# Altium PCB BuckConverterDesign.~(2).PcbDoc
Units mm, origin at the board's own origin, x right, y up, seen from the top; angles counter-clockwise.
Board outline 71.7 x 34.6 mm, 4 copper layers (Top Layer, IN-1, IN-2, Bottom Layer), stack 0.603 mm thick; 42 components, 34 nets, 154 pads, 18 vias.
Unrouted connection lines stored in the file: 68.
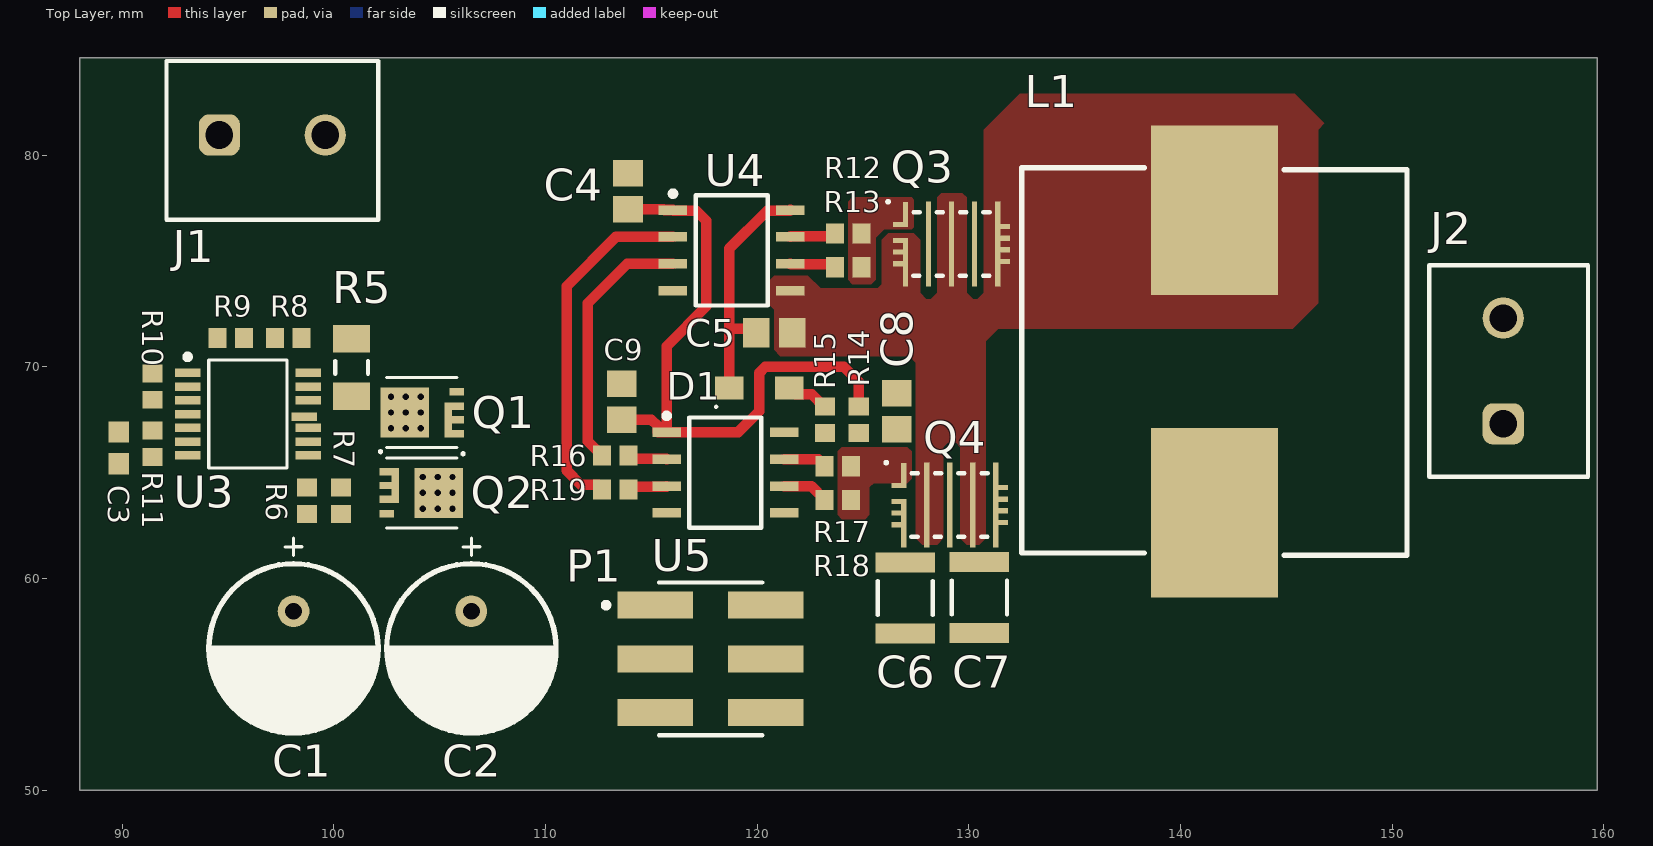
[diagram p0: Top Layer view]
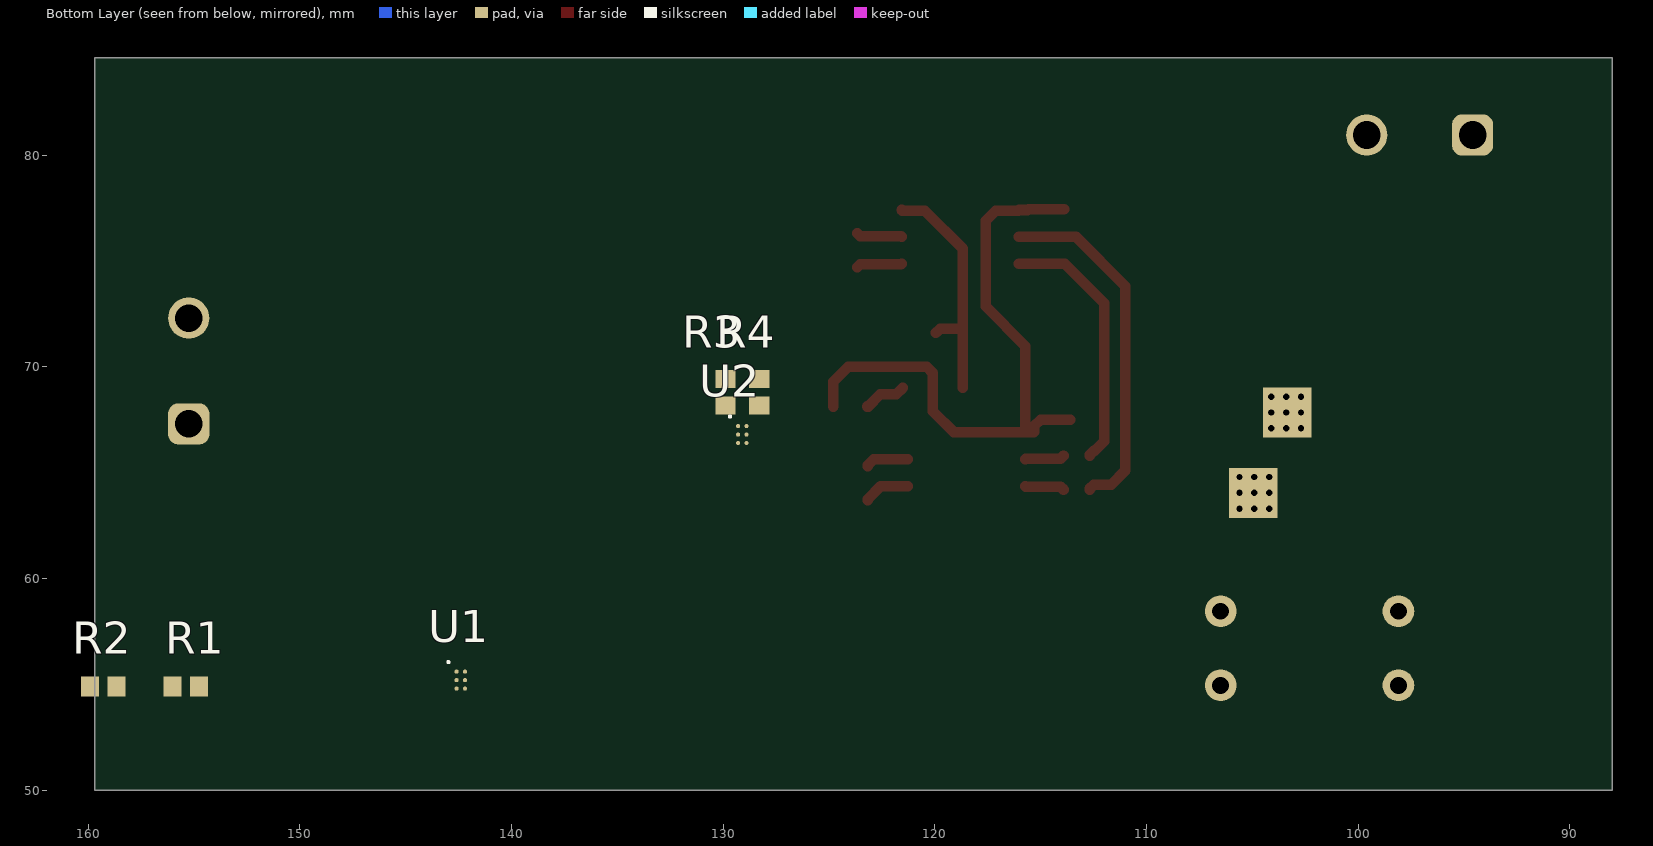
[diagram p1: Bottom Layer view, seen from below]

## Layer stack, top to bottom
Top Solder: solder mask 0.0102, Solder Resist, Dk 3.5
Top Layer: signal copper 0.035
Dielectric 2: prepreg 0.0711, PP-006, Dk 4.1
IN-1: signal copper 0.0356
Dielectric 1: dielectric 0.32, FR-4, Dk 4.8
IN-2: signal copper 0.0356
Dielectric 3: prepreg 0.0711, PP-006, Dk 4.1
Bottom Layer: signal copper 0.035
Bottom Solder: solder mask 0.0102, Solder Resist, Dk 3.5

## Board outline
88,50 159.7,50 159.7,84.6 88,84.6

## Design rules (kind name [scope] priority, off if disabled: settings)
AssemblyTestPointUsage [All] p1: isadvanced=TRUE
AssemblyTestpoint [All] p1: isadvanced=TRUE testpointundercomponent=TRUE minsize=1.016 maxsize=2.54 preferedsize=1.524 minholesize=0 maxholesize=1.016 preferedholesize=0.813 testpointgrid=0.025 usegrid=TRUE gridtolerance=0 allowsidetop=TRUE allowsidebottom=TRUE
Clearance Clearance_1 [All] p1: isadvanced=TRUE gap=0.15 ignorepadtopadclearanceinfootprint=FALSE
Clearance [All] p2: gap=0.254 ignorepadtopadclearanceinfootprint=FALSE ismatrix=TRUE
ComponentClearance [All] p1: isadvanced=TRUE gap=0.254 collisioncheckmode=3 verticalgap=0.254 showdistances=FALSE
FabricationTestPointUsage [All] p1: isadvanced=TRUE valid=0 allowmultiple=FALSE
FabricationTestpoint [All] p1: isadvanced=TRUE side=3 testpointundercomponent=TRUE minsize=1.016 maxsize=2.54 preferedsize=1.524 minholesize=0 maxholesize=1.016 preferedholesize=0.813 testpointgrid=0.025 allowsidetop=TRUE allowsidebottom=TRUE usegrid=TRUE gridtolerance=0
FanoutControl Fanout_BGA [IsBGA] p1: isadvanced=TRUE bgadir=Out bgaviamode=Centered fanoutstyle=Auto fanoutdirection=Alternating viagrid=0.025 // Fanout_BGA (Default Rule)
FanoutControl Fanout_LCC [IsLCC] p2: isadvanced=TRUE bgadir=Out bgaviamode=Centered fanoutstyle=Auto fanoutdirection=Alternating viagrid=0.025 // Fanout_LCC (Default Rule)
FanoutControl Fanout_SOIC [IsSOIC] p3: isadvanced=TRUE bgadir=Out bgaviamode=Centered fanoutstyle=Auto fanoutdirection=Alternating viagrid=0.025 // Fanout_SOIC (Default Rule)
FanoutControl Fanout_Small [(CompPinCount < 5)] p4: isadvanced=TRUE bgadir=Out bgaviamode=Centered fanoutstyle=Auto fanoutdirection=OutThenIn viagrid=0.025 // Fanout_Small (Default Rule)
FanoutControl Fanout_Default [All] p5: isadvanced=TRUE bgadir=Out bgaviamode=Centered fanoutstyle=Auto fanoutdirection=Alternating viagrid=0.025 // Fanout_Default (Default Rule)
Height [All] p1: isadvanced=TRUE minheight=0 maxheight=25.4 prefheight=12.7
HoleSize [All] p1: isadvanced=TRUE absolutevalues=TRUE maxlimit=20 minlimit=0.3 maxpercent=80.000 minpercent=20.000
HoleToHoleClearance [All] p1: isadvanced=TRUE gap=0.3 allowstackedmicrovias=TRUE
LayerPairs [All] p1: isadvanced=TRUE enforce=TRUE
MinimumSolderMaskSliver [All] p1: isadvanced=TRUE minsoldermaskwidth=0.15
NetAntennae [All] p1: isadvanced=TRUE netantennaetolerance=0
PasteMaskExpansion [All] p1: isadvanced=TRUE expansion=0.1 thpadusetoppaste=TRUE thpadusebottompaste=TRUE
PlaneClearance [All] p1: isadvanced=TRUE clearance=0.508
PlaneConnect [All] p1: isadvanced=TRUE planeconnectstyle=Relief reliefexpansion=0.508 reliefentries=4 reliefconductorwidth=0.254 reliefairgap=0.254
RoutingCorners [All] p1: isadvanced=TRUE cornerstyle=45-Degree minsetback=2.54 maxsetback=2.54
RoutingPriority [All] p1: isadvanced=TRUE routingpriority=0
RoutingTopology RoutingTopology_1 [All] p1: isadvanced=TRUE topology=Daisy_Balanced
RoutingVias RoutingViaStyle_1 [All] p1: isadvanced=TRUE holewidth=0.3 width=0.5 viastyle="Through Hole" minholewidth=0.3 minwidth=0.5 maxholewidth=10 maxwidth=20
RoutingVias [All] p2: holewidth=0.711 width=1.27 viastyle="Through Hole" minholewidth=0.711 minwidth=1.27 maxholewidth=0.711 maxwidth=1.27
ShortCircuit [All] p1: isadvanced=TRUE allowed=FALSE
SilkToSilkClearance [All] p1: isadvanced=TRUE silktosilkclearance=0.15
SilkToSolderMaskClearance [IsPad] p1: isadvanced=TRUE minsilkscreentomaskgap=0.15 clearancetoexposedcopper=TRUE
SolderMaskExpansion [All] p1: isadvanced=TRUE expansion=0.102 istentingtop=TRUE
SupplyNets "Schematic Supply Nets_13" [InNet('VOUT')] p1: voltage=0.000
SupplyNets "Schematic Supply Nets_12" [InNet('3V3')] p2: voltage=0.000
SupplyNets "Schematic Supply Nets_11" [InNet('VIN')] p3: voltage=0.000
SupplyNets "Schematic Supply Nets_10" [InNet('OUT')] p4: voltage=0.000
SupplyNets "Schematic Supply Nets_9" [InNet('5V')] p5: voltage=0.000
SupplyNets "Schematic Supply Nets_2" [InNet('GND')] p6: voltage=0.000
SupplyNets "Schematic Supply Nets_1" [InNet('SW Node')] p7: voltage=0.000
UnRoutedNet [All] p1: isadvanced=TRUE
UnpouredPolygon [All] p1 off: isadvanced=TRUE
Width MaxMinWidth_1 [All] p1: isadvanced=TRUE maxlimit=10 minlimit=0.15 preferedwidth=0.3 minimp=50.000000 maximp=50.000000 favimp=50.000000
3 further rules are at their usual default settings.

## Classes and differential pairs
component class [06]TemperatureSense: R9 R10 R15 U1
component class [00]Connectors: P1
component class [05]BuckConverter: C4 C5 C6 C7 C8 C9 D1 J2 L1 Q3 Q4 R15 R18 R19 U5
component class [02]PowerProtections: C1 C2 C3 J1 Q1 Q2 R9 R10 R15 U1

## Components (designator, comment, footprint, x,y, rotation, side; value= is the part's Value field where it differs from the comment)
C1 "AlPolTHT 100 µF 63V 0603 X7R ±10%" 107AVG063MFBJ 98.1,56.7 r270 top
C2 "AlPolTHT 100 µF 63V 0603 X7R ±10%" 107AVG063MFBJ 106.5,56.7 r270 top
C3 "CerSMD 10nF 16V 0603 X7R ±10%" CAPC1608X09N 89.844,66.168 r270 top
C4 "CerSMD 100nF 16V 0805 X7R ±10%" CAPC2012X09N 113.9,78.3 r90 top
C5 "CerSMD 220nF 50V 0805 X7R ±10%" CAPC2012X09N 120.8,71.6 r0 top
C6 "CerSMD 3.3µF 100V 1210 X7S ±10%" CAPC3225X28N 127,59.075 r90 top
C7 "CerSMD 3.3µF 100V 1210 X7S ±10%" CAPC3225X28N 130.5,59.1 r90 top
C8 "CerSMD 2.2 µF 16V 0805 X7R ±10%" CAPC2012X09N 126.6,67.9 r90 top
C9 "CerSMD 100nF 16V 0805 X7R ±10%" CAPC2012X09N 113.6,68.35 r90 top
D1 "MBR1H100SFT3G" SODFL360X95-2N 120.1,69 r180 top
J1 "691137710002" 691137710002 97.1,80.7 r0 top
J2 "691137710002" 691137710002 155.5,69.8 r90 top
L1 "IndSMD Shielded 7.6 µH 20A 20.5 3.75 mOhm" 7443557760 132.5,61.2 r0 top
P1 "5-146130-2" TECO-5-146130-2_V 117.8,56.2 r270 top
Q1 "BSZ040N06LS5ATMA1" PG-TSDSON-8-FL 105.808,66.191 r90 top
Q2 "BSZ040N06LS5ATMA1" PG-TSDSON-8-FL 102.508,65.691 r270 top
Q3 "IGC019S06S1XTMA1" IGC019S06S1XTMA1 126.688,77.3 r270 top
Q4 "IGC019S06S1XTMA1" IGC019S06S1XTMA1 126.599,64.971 r270 top
R1 "SMDRes 10K 0603 %1 0.1W" RESC1508X06N 155.4,54.9 r180 bottom
R2 "SMDRes 10K 0603 %1 0.1W" RESC1508X06N 159.3,54.9 r180 bottom
R3 "SMDRes 10K 0603 %1 0.1W" RESC1508X06N 129.9,68.8 r90 bottom
R4 "SMDRes 10K 0603 %1 0.1W" RESC1508X06N 128.3,68.8 r90 bottom
R5 "SMDRes 5 mOhm 1206 %1 1W" RESC3116X10N 100.844,69.968 r270 top
R6 "SMDRes 470K 0603 %1 0.1W" RESC1508X06N 98.744,63.668 r270 top
R7 "SMDRes 470K 0603 %1 0.1W" RESC1508X06N 100.344,63.668 r270 top
R8 "SMDRes 374K 0603 %1 0.1W" RESC1508X06N 97.844,71.368 r180 top
R9 "SMDRes 1.82K 0603 %1 0.1W" RESC1508X06N 95.144,71.368 r0 top
R10 "SMDRes 47K 0603 %1 0.1W" RESC1508X06N 91.444,69.068 r90 top
R11 "SMDRes 10K 0603 %1 0.1W" RESC1508X06N 91.444,66.368 r270 top
R12 "SMDRes 10 Ohm 0603 %1 0.1W" RESC1508X06N 124.3,76.3 r0 top
R13 "SMDRes 2 Ohm 0603 %1 0.1W" RESC1508X06N 124.3,74.7 r0 top
R14 "SMDRes 10 Ohm 0603 %1 0.1W" RESC1508X06N 124.8,67.5 r90 top
R15 "SMDRes 2.2 Ohm 0603 %1 0.1W" RESC1508X06N 123.2,67.5 r90 top
R16 "SMDRes 33 kOhm 0603 %1 0.1W" RESC1508X06N 113.3,65.8 r0 top
R17 "SMDRes 10 Ohm 0603 %1 0.1W" RESC1508X06N 123.8,65.3 r0 top
R18 "SMDRes 2 Ohm 0603 %1 0.1W" RESC1508X06N 123.8,63.7 r0 top
R19 "SMDRes 33 kOhm 0603 %1 0.1W" RESC1508X06N 113.3,64.2 r0 top
U1 "TMP119AIYBGR" BGA6C40P2X3_95X149X52 142.4,55.2 r180 bottom
U2 "TMP119AIYBGR" BGA6C40P2X3_95X149X52 129.1,66.8 r180 bottom
U3 "TPS2492PWR" TSOP65P640X120-14L 95.944,67.768 r0 top
U4 "1EDB7275FXUMA1" SOIC127P600X175-8N 118.8,75.5 r0 top
U5 "1EDB7275FXUMA1" SOIC127P600X175-8N 118.5,65 r0 top

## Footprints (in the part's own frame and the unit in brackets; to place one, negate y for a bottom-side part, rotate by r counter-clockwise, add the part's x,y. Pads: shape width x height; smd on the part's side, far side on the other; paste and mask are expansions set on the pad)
107AVG063MFBJ [mm] "8mm Diameter  13..5mm Height 3.5mm Pitch"
  round 1.5 hole 0.8: 1(-1.75,0) 2(1.75,0)
  silkscreen extent -5.2,-4 4,4, body extent -4,-4 4,4, height 13.85
7443557760 [mm]
  rect 6x8 smd: 1(9.1,16.2) 2(9.1,1.9)
  silkscreen extent 0,-0.1 18.2,18.2, body extent 0,-0.1 18.2,18.2, height 8.85
691137710002 [mm] "Horizontal Cable Entry with Pressure Clamp, pitch 5mm, 02p"
  rrect50% 1.95x1.95 hole 1.3: 1(-2.5,0.25)
  round 1.95 hole 1.3: 2(2.5,0.25)
  silkscreen extent -5,-3.75 5,3.75, body extent -5,-3.75 5,3.75, height 11.6
BGA6C40P2X3_95X149X52 [mm] "BGA, 6-Leads, Body 0.95x1.49mmx0.53mm, Pitch 0.40mm"
  round 0.2 smd: A1(-0.2,0.4) A2(0.2,0.4) B1(-0.2,0) B2(0.2,0) C1(-0.2,-0.4) C2(0.2,-0.4)
  silkscreen extent -0.63,0.8 -0.53,0.9, body extent -0.48,-0.74 0.48,0.74, height 0.53
CAPC1608X09N [mm] "Chip Capacitor, 2-Leads, Body 1.60x0.80mm, IPC Medium Density"
  rect 1x0.95 smd: 1(-0.75,0) 2(0.75,0)
  body extent -0.85,-0.45 0.85,0.45, height 0.9
CAPC2012X09N [mm] "Chip Capacitor, 2-Leads, Body 2.00x1.25mm, IPC Medium Density"
  rect 1.25x1.4 smd: 1(-0.85,0) 2(0.85,0)
  body extent -1.07,-0.67 1.07,0.67, height 0.9
CAPC3225X28N [mm] "Chip Capacitor, 2-Leads, Body 3.20x2.50mm, IPC Medium Density"
  rect 0.95x2.8 smd: 1(-1.675,0) 2(1.675,0)
  silkscreen extent -0.8,-1.3 0.8,1.3, body extent -1.8,-1.4 1.8,1.4, height 2.8
IGC019S06S1XTMA1 [mm] "PG-TSON-6-2"
  rect 1.2x0.25 smd: 1(0.107,0.325)
  rect 0.25x0.7 smd: 1(0.582,0.09) 5(0.675,4.91) 5(1.225,4.91) 5(1.775,4.91) 5(2.325,4.91) 6(1.332,0.09) 6(1.882,0.09) 6(2.432,0.09)
  rect 4x0.25 smd: 2(1.5,1.412) 3(1.5,2.5) 4(1.5,3.587) 5(1.5,4.675)
  rect 2.3x0.25 smd: 6(2.357,0.325)
  silkscreen extent -0.56,-0.56 3,4.3, body extent 0,0 3,5, height 1.04
PG-TSDSON-8-FL [mm]
  rect 0.35x0.7 smd: 1(0.65,0) 1(1.3,0) 1(1.95,0) 2(2.625,0)
  rect 1.65x0.35 smd: 1(1.3,0.4)
  rect 2.35x2.3 smd: 3(1.65,2.45)
  rect 2.35x2.3 smd far side: 3(1.65,2.45)
  silkscreen extent -0.35,-0.35 3.3,3.3, body extent 0,0 3.3,3.3, height 1.11
RESC1508X06N [mm] "Chip Resistor, 2-Leads, Body 1.55x0.80mm, IPC Medium Density"
  rect 0.85x0.95 smd: 1(-0.625,0) 2(0.625,0)
  body extent -0.85,-0.48 0.85,0.48, height 0.6
RESC3116X10N [mm] "Chip Resistor, 2-Leads, Body 3.10x1.55mm, IPC Medium Density"
  rect 1.3x1.75 smd: 1(-1.35,0) 2(1.35,0)
  silkscreen extent -0.3,-0.77 0.3,0.77, body extent -1.65,-0.87 1.65,0.87, height 0.95
SODFL360X95-2N [mm] "SODFL, 2-Leads, Body 1.65x3.60mm, IPC Medium Density"
  rect 1.35x1.1 smd: 1(-1.425,0) 2(1.425,0)
  silkscreen extent 1.98,0.84 2.08,0.94, body extent -1.8,-0.9 1.8,0.9, height 0.95
SOIC127P600X175-8N [mm] "SOIC, 8-Leads, Body 5.00x4.00mm, Pitch 1.27mm, IPC Medium Density"
  rect 1.35x0.45 smd: 1(-2.775,1.905) 2(-2.775,0.635) 3(-2.775,-0.635) 4(-2.775,-1.905) 5(2.775,-1.905) 6(2.775,-0.635) 7(2.775,0.635) 8(2.775,1.905)
  silkscreen extent -2.9,-2.6 1.7,2.8, body extent -3,-2.6 3,2.6, height 1.75
TECO-5-146130-2_V [mm] "Header, 6-Leads, Body 7.21x4.88mm, Pitch 2.54mm"
  rect 1.27x3.56 smd: 1(-2.54,-2.605) 2(-2.54,2.605) 3(0,-2.605) 4(0,2.605) 5(2.54,-2.605) 6(2.54,2.605)
  silkscreen extent -3.6,-5.06 3.6,2.44, body extent -3.61,-3.77 3.61,3.64, height 9.74
TSOP65P640X120-14L [mm] "TSOP, 14-Leads, Body 5.00x4.40mm, Pitch 0.65mm, IPC High Density"
  rect 1.2x0.4 smd: 1(-2.85,1.95) 2(-2.85,1.3) 3(-2.85,0.65) 4(-2.85,0) 5(-2.85,-0.65) 6(-2.85,-1.3) 7(-2.85,-1.95) 8(2.85,-1.95) 9(2.85,-1.3) 10(2.85,-0.65) 11(2.667,-0.127) 12(2.85,0.65) 13(2.85,1.3) 14(2.85,1.95)
  silkscreen extent -2.97,-2.55 1.85,2.82, body extent -3.2,-2.5 3.2,2.5, height 1.21

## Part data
C1 C2: library part CMP-00002-4, "Ceramic Capacitor SMD 100 µF 63V 0603 X7R ±10%", Digi-Key Part Number=1572-1656-ND, Manufacturer="Cornell Dubilier Knowles", Manufacturer Number=107AVG063MFBJ, Mouser Part Number=598-107AVG063MFBJ, Package=0603, Temperature="-55°C up to 125°C", Temperature Coefficient=X7R, Tolerance=±10%, Voltage=63V
C3: library part CMP-00001-3, "Ceramic Capacitor SMD  10nF 16V 0603 X7R ±10%", Digi-Key Part Number=1276-CL10B103KO8WPNCCT-ND, Manufacturer="Samsung Electro-Mechanics", Manufacturer Number=CL10B103KO8WPNC, Mouser Part Number=187-CL10B103KO8WPNC, Package=0603, Temperature="-55°C up to 125°C", Temperature Coefficient=X7R, Tolerance=±10%, Voltage=16V
C4 C9: library part CMP-00013-1, "Ceramic Capacitor SMD 100nF 10V 0805 X7R ±10%", Digi-Key Part Number=732-8026-1-ND, Farnell Part Number=2534051, Manufacturer="Würth Elektronik", Manufacturer Number=885012207016, Mouser Part Number=710-885012207016, Package=0603, Temperature="-55°C up to 125°C", Temperature Coefficient=X7R, Tolerance=±10%, Voltage=10V
C5: library part CMP-00016-1, "Ceramic Capacitor SMD 220nF 50V 0805 X7R ±10%", Digi-Key Part Number=490-1670-1-ND, Manufacturer="Murata Electronics", Manufacturer Number=GRM21BR71H224KA01L, Mouser Part Number=81-GRM40X7R224K050AL, Package=0805, Temperature="-55°C up to 125°C", Temperature Coefficient=X7R, Tolerance=±10%, Voltage=10V
C6 C7: library part CMP-00010-1, "Ceramic Capacitor SMD 3.3µF 100V 1210 X7S ±10%", Digi-Key Part Number=445-5209-1-ND, Manufacturer="Samsung Electro-Mechanics", Manufacturer Number=C3225X7S2A335K200AB, Mouser Part Number=810-C3225X7S2A335K, Package=0603, Temperature="-55°C up to 125°C", Temperature Coefficient=X7R, Tolerance=±10%, Voltage=16V
C8: library part CMP-00014-1, "Ceramic Capacitor SMD 2.2 µF 16V 0805 X7R ±10%", Digi-Key Part Number=445-1420-1-ND, Farnell Part Number=1907345, Manufacturer="TDK Corporation", Manufacturer Number=C2012X7R1C225K125AB, Mouser Part Number=810-C2012X7R1C225K, Package=0805, Temperature="-55°C up to 125°C", Temperature Coefficient=X7R, Tolerance=±10%, Voltage=16V
D1: library part CMP-00020-2
J1 J2: library part CMP-00022-1, "würth terminal"
L1: library part CMP-00011-1, "Inductor SMD Shielded 7.6 µH 20A 20.5 3.75 mOhm"
P1: library part CMP-002-00018-2, "Male Header, Pitch 2.54 mm, 2 x 3 Position, Height 8.13 mm, -65 to 125 degC, RoHS, Tube", Manufacturer="TE Connectivity", Max Operating Temperature=125°C, Min Operating Temperature=-65°C, Package Description="Male Header, Pitch 2.54 mm, 2 x 3 Position, Height 8.13 mm"
Q1 Q2: library part CMP-00004-1, "N-MOS 60V 17A (Ta) 101A (Tc)"
Q3 Q4: library part CMP-00009-1, "GaNFET N-Ch - 60V - 27A (Ta), 99A (Tc)", Digi-Key Part Number=448-IGC019S06S1XTMA1CT-ND, Drive Voltage=5V, Farnell Part Number=4680815, Manufacturer="Infineon Technologies", Mouser Part Number=726-IGC019S06S1XTMA1, Operating Temperature="-40°C up to 150°C (TJ)", Package=PG-TSON-6-2
R1 R2 R3 R4: library part CMP-00001-1-2, "Res Thick Film 0603 10K Ohm 1% 0.1W(1/10W) ±100ppm/C Pad SMD T/R Automotive AEC-Q200", Digi-Key Part Number=RMCF0603FT10K0CT-ND, Manufacturer="Stackpole Electronics Inc", Manufacturer Number=RMCF0603FT10K0, Mouser Part Number=708-RMCF0603FT10K0, Package=0603, Power=0.1W, Temperature="-55°C up to 155°C", Tolerance=±1%
R5: library part CMP-00007-2, "5 mOhms ±1% 1W Chip Resistor 1206 (3216 Metric) Automotive AEC-Q200, Current Sense, Moisture Resistant Metal Foil", Digi-Key Part Number=CSRF1206FT5L00CT-ND, Manufacturer="Stackpole Electronics Inc", Manufacturer Number=CSRF1206FT5L00, Mouser Part Number=708-CSRF1206FT5L00, Package=1206, Power=1W, Temperature="-55°C up to 170°C", Tolerance=±1%
R6 R7: library part CMP-00006-1, "Res Thick Film 0603 470K Ohm 1% 0.1W(1/10W) ±100ppm/C Pad SMD T/R Automotive AEC-Q200", Digi-Key Part Number=RMCF0603FT470KCT-ND, Manufacturer="Stackpole Electronics Inc", Manufacturer Number=RMCF0603FT470K, Mouser Part Number=708-RMCF0603FT470K, Package=0603, Power=0.1W, Temperature="-55°C up to 155°C", Tolerance=±1%
R8: library part CMP-00005-2, "Res Thick Film 0603 374K Ohm 1% 0.1W(1/10W) ±100ppm/C Pad SMD T/R Automotive AEC-Q200", Digi-Key Part Number=RMCF0603FT374KCT-ND, Manufacturer="Stackpole Electronics Inc", Manufacturer Number=RMCF0603FT374K, Mouser Part Number=708-RMCF0603FT374K, Package=0603, Power=0.1W, Temperature="-55°C up to 155°C", Tolerance=±1%
R9: library part CMP-00003-2, "Res Thick Film 0603 1.82K Ohm 1% 0.1W(1/10W) ±100ppm/C Pad SMD T/R Automotive AEC-Q200", Digi-Key Part Number=RMCF0603FT1K82CT-ND, Manufacturer="Stackpole Electronics Inc", Manufacturer Number=RMCF0603FT1K82, Mouser Part Number=708-RMCF0603FT1K82, Package=0603, Power=0.1W, Temperature="-55°C up to 155°C", Tolerance=±1%
R10: library part CMP-00008-1, "Res Thick Film 0603 47K Ohm 1% 0.1W(1/10W) ±100ppm/C Pad SMD T/R Automotive AEC-Q200", Digi-Key Part Number=RMCF0603FT47K0CT-ND, Manufacturer="Stackpole Electronics Inc", Manufacturer Number=RMCF0603FT47K0, Mouser Part Number=708-RMCF0603FT47K0, Package=0603, Power=0.1W, Temperature="-55°C up to 155°C", Tolerance=±1%
R11: library part CMP-00001-1-1, "Res Thick Film 0603 10K Ohm 1% 0.1W(1/10W) ±100ppm/C Pad SMD T/R Automotive AEC-Q200", Digi-Key Part Number=RMCF0603FT10K0CT-ND, Manufacturer="Stackpole Electronics Inc", Manufacturer Number=RMCF0603FT10K0, Mouser Part Number=708-RMCF0603FT10K0, Package=0603, Power=0.1W, Temperature="-55°C up to 155°C", Tolerance=±1%
R12 R14 R17: library part CMP-00017-1, "Res Thick Film 0603 10 Ohm Ohm 1% 0.1W(1/10W) ±100ppm/C Pad SMD T/R Automotive AEC-Q200", Digi-Key Part Number=RMCF0603FT10R0CT-ND, Manufacturer="Stackpole Electronics Inc", Manufacturer Number=RMCF0603FT10R0, Mouser Part Number=708-RMCF0603FT10R0, Package=0603, Power=0.1W, Temperature="-55°C up to 155°C", Tolerance=±1%
R13 R18: library part CMP-00019-1, "Res Thick Film 0603 2 Ohm Ohm 1% 0.1W(1/10W) ±100ppm/C Pad SMD T/R Automotive AEC-Q200", Digi-Key Part Number=RMCF0603FT2R00CT-ND, Manufacturer="Stackpole Electronics Inc", Manufacturer Number=RMCF0603FT2R00, Mouser Part Number=708-RMCF0603FT2R00, Package=0603, Power=0.1W, Temperature="-55°C up to 155°C", Tolerance=±1%
R15: library part CMP-00015-1, "Res Thick Film 0603 2.2 Ohm Ohm 1% 0.1W(1/10W) ±100ppm/C Pad SMD T/R Automotive AEC-Q200", Digi-Key Part Number=RMCF0603FT2R20CT-ND, Manufacturer="Stackpole Electronics Inc", Manufacturer Number=RMCF0603FT2R20, Mouser Part Number=708-RMCF0603FT2R20, Package=0603, Power=0.1W, Temperature="-55°C up to 155°C", Tolerance=±1%
R16 R19: library part CMP-00018-1, "Res Thick Film 0603 33 kOhm Ohm 1% 0.1W(1/10W) ±100ppm/C Pad SMD T/R Automotive AEC-Q200", Digi-Key Part Number=RMCF0603FT33K0CT-ND, Manufacturer="Stackpole Electronics Inc", Manufacturer Number=RMCF0603FT33K0, Mouser Part Number=708-RMCF0603FT33K0, Package=0603, Power=0.1W, Temperature="-55°C up to 155°C", Tolerance=±1%
U1 U2: library part CMP-00021-1, "Temperature Sensor"
U3: library part CMP-00000-1, "eFuses - External MOSFETs - 9V-80V", Digi-Key Part Number=296-39373-1-ND, Manufacturer="Texas Instruments", Mouser Part Number=595-TPS2492PWR, Package=14-TSSOP, Temperature Rating="-40°C up to 125°C", Voltage Rating="9V up to 80V"
U4 U5: library part CMP-00012-1

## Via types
v1: diameter 0.5, hole 0.3, Top Layer to Bottom Layer, tented both sides, 18 vias

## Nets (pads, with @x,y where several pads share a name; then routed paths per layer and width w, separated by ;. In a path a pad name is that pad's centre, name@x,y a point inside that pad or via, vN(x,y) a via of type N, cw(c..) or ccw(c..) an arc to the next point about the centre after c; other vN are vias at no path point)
3V3: C4.1 C9.1 P1.6 R1.2 R2.2 R3.2 R4.2 R6.2 R7.2 R14.2 U1.B1 U2.B1 U4.1 U5.1 | length 30.1
  Top Layer w0.5: C9.1 115.007,67.5 115.3,67.207 115.3,66.93 115.325,66.905 U5.1 ; C4.1 115.58,77.45 115.625,77.405 U4.1 116.05,77.38 117.12,77.38 117.6,76.9 117.6,72.853 115.725,70.978 U5.1 ; R14.2 124.8,69.3 124.1,70 120.393,70 120.1,69.707 120.1,67.9 119.1,66.9 115.73,66.9 U5.1
5V: C5.1 D1.2 P1.5 U4.8 | length 11.6
  Top Layer w0.5: D1.2 118.675,71.8 ; C5.1 119.75,71.8 118.675,71.8 ; U4.8 121.55,77.38 120.48,77.38 118.675,75.575 118.675,71.8
GND: C1.2 C2.2 C3.2 C4.2 C6.2 C7.2 C8.2 C9.2 J1.1 J2.2 Q4.3 Q4.5 Q4.6 R11.2 U1.B2 U1.C1 U2.B2 U2.C1 U3.7 U4.4 U5.4 U5.5
NetC3_1: C3.1 U3.4
NetC8_1: C8.1 R14.1 R15.1 U5.8
NetD1_1: D1.1 R15.2 | length 2
  Top Layer w0.5: D1.1 121.825,68.7 122.575,68.7 123.15,68.125 R15.2
NetJ1_2: J1.2 R5.1 R8.1 U3.14
NetP1_1: P1.1 R16.1 U4.3 | length 12.3
  Top Layer w0.5: R16.1 112.675,65.85 112.5,66.025 112.45,66.025 112,66.475 112,73 113.865,74.865 U4.3
NetP1_2: P1.2 R1.1 R3.1 U1.A1 U2.A1
NetP1_3: P1.3 R19.1 U4.2 | length 16.8
  Top Layer w0.5: R19.1 112.675,64.25 112.5,64.425 111.675,64.425 111,65.1 111,73.8 113.335,76.135 U4.2
NetP1_4: P1.4 R2.1 R4.1 U1.A2 U2.A2
NetQ1_1: Q1.1 Q2.1 U3.11
NetQ1_2: Q1.2 Q2.2 U3.12
NetQ1_3: Q1.3 R5.2 U3.13
  other v1: 102.708,67.091 103.408,67.091 104.108,67.091 102.708,67.841 103.408,67.841 104.108,67.841 102.708,68.591 103.408,68.591 104.108,68.591
NetQ3_1: Q3.1 R12.2 R13.2
NetQ4_1: Q4.1 R17.2 R18.2
NetR6_1: R6.1 U3.8
NetR7_1: R7.1 U3.9
NetR8_2: R8.2 R9.2 U3.1
NetR9_1: R9.1 R11.1 U3.5
NetR10_1: R10.1 U3.3
NetR10_2: R10.2 U3.2
NetR12_1: R12.1 U4.7 | length 2.2
  Top Layer w0.5: U4.7 121.6,76.16 123.535,76.16 R12.1
NetR13_1: R13.1 U4.6 | length 2.2
  Top Layer w0.5: U4.6 121.6,74.84 123.535,74.84 R13.1
NetR16_2: R16.2 U5.2 | length 1.9
  Top Layer w0.5: R16.2 114.065,65.66 115.7,65.66 U5.2
NetR17_1: R17.1 U5.7 | length 2.1
  Top Layer w0.5: U5.7 122.89,65.635 123.175,65.35 R17.1
NetR18_1: R18.1 U5.6 | length 2.2
  Top Layer w0.5: U5.6 122.56,64.365 123.175,63.75 R18.1
NetR19_2: R19.2 U5.3 | length 1.9
  Top Layer w0.5: R19.2 114.065,64.34 115.7,64.34 U5.3
NetU1_C2: U1.C2
NetU2_C2: U2.C2
OUT: C6.1 C7.1 J2.1 L1.2
"SW Node": C5.2 L1.1 Q3.3 Q3.5 Q3.6 Q4.2 Q4.4 U4.5
VIN: C1.1 C2.1 Q2.3
  other v1: 104.208,63.291 104.908,63.291 105.608,63.291 104.208,64.041 104.908,64.041 105.608,64.041 104.208,64.791 104.908,64.791 105.608,64.791
VOUT: Q3.2 Q3.4
pads on no net: U3.6 U3.10

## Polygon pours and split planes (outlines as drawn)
"SW Node" on Top Layer "SW_NODE_L01_P000" (solid, pour order 0): 121.1,70.5 120.8,70.8 120.8,72.7 120.5,73 120.5,74 120.8,74.3 122.4,74.3 123,73.7 125.7,73.7 125.9,73.9 125.9,76 126.2,76.3 127.4,76.3 127.7,76 127.7,73.5 128,73.2 128.2,73.2 128.5,73.5 128.5,78 128.7,78.2 129.7,78.2 129.9,78 129.9,73.5 130.2,73.2 130.4,73.2 130.7,73.5 130.7,81.2 132.4,82.9 145.4,82.9 146.5,81.8 146.5,81.2 146.5,73 145.3,71.8 131.4,71.8 130.8,71.2 130.8,61.9 130.5,61.6 129.9,61.6 129.6,61.9 129.6,66.2 129.4,66.4 129,66.4 128.8,66.2 128.8,61.9 128.5,61.6 127.8,61.6 127.5,61.9 127.5,66.1 127.5,70.2 127.2,70.5 121.1,70.5 121.1,70.4
NetQ3_1 on Top Layer "NETQ3_1_L01_P001" (solid, pour order 1): 124.3,74.1 124.5,73.9 125.4,73.9 125.6,74.1 125.6,76.1 126,76.5 127.3,76.5 127.4,76.6 127.4,77.9 127.3,78 124.5,78 124.3,77.8
NetQ4_1 on Top Layer "NETQ4_1_L01_P002" (solid, pour order 2): 124,62.8 123.8,63 123.8,66 124,66.2 127.1,66.2 127.3,66 127.3,64.7 127.1,64.5 125.5,64.5 125.3,64.3 125.3,63 125.1,62.8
